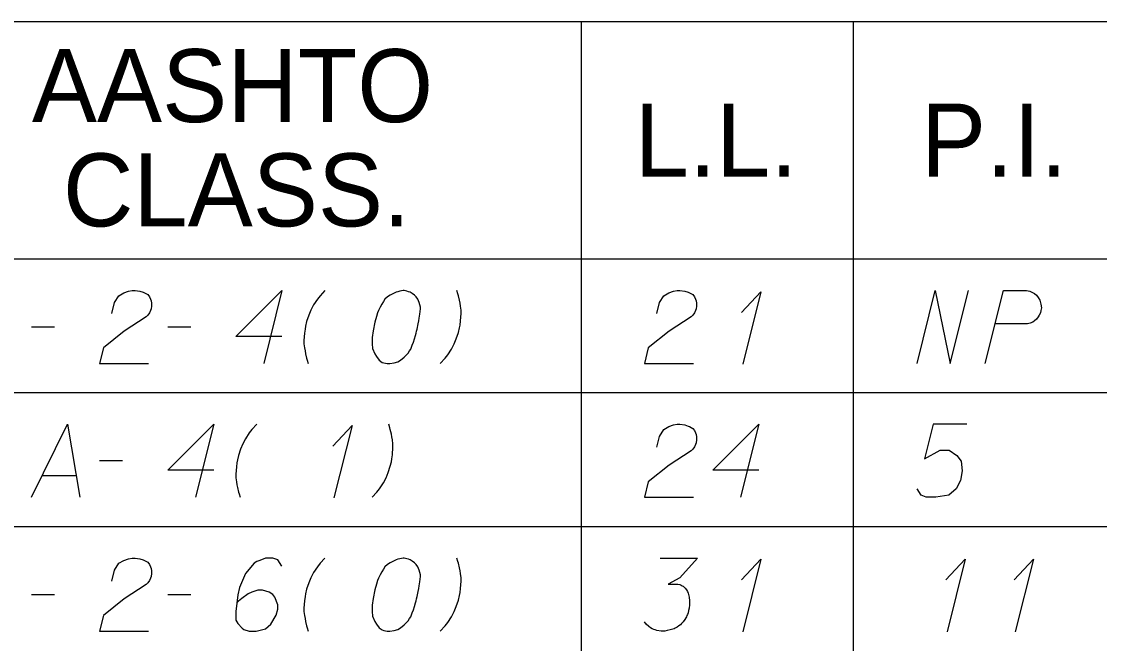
# Model space of a CAD drawing. Extents: x 2074207 to 2076812, y 516372 to 523312.
# Drawn here: x 2076453.5 to 2076524.4, y 517338.3 to 517379.2 of the extents above; entities that cross this region are included whole.
import ezdxf

# ---------------------------------------------------------------- set-up
doc = ezdxf.new("R2010")
doc.units = 0
for name, color, linetype in [('Prop DirtTable_ Soil Test Results - Outline (Major)', 7, 'Continuous'), ('Prop DirtTable_ Soil Test Results - Outline (Minor)', 7, 'Continuous'), ('Prop DirtTable_ Soil Test Results - Tx (Header - Small)', 7, 'Continuous'), ('Prop DirtTable_ Soil Test Results - Tx (Sample Data)', 7, 'Continuous')]:
    doc.layers.add(name, color=color, linetype=linetype)

msp = doc.modelspace()

# ---------------------------------------------------------------- linework, layer by layer
at = {"layer": 'Prop DirtTable_ Soil Test Results - Outline (Major)'}
msp.add_line((2076260.609, 517363.585), (2076811.903, 517363.585), dxfattribs=at)
msp.add_line((2076260.609, 517363.585), (2076811.903, 517363.585), dxfattribs=at)
at = {"layer": 'Prop DirtTable_ Soil Test Results - Outline (Minor)'}
for p, q in [((2076260.609, 517379.185), (2076811.903, 517379.185)), ((2076490.31, 517379.185), (2076490.31, 517354.785)), ((2076508.192, 517379.185), (2076508.192, 517354.785)), ((2076260.609, 517354.785), (2076811.903, 517354.785)), ((2076260.609, 517354.785), (2076811.903, 517354.785)), ((2076490.31, 517354.785), (2076490.31, 517345.985)), ((2076508.192, 517354.785), (2076508.192, 517345.985)), ((2076260.609, 517345.985), (2076811.903, 517345.985)), ((2076260.609, 517345.985), (2076811.903, 517345.985)), ((2076490.31, 517345.985), (2076490.31, 517337.185)), ((2076508.192, 517345.985), (2076508.192, 517337.185))]:
    msp.add_line(p, q, dxfattribs=at)
at = {"layer": 'Prop DirtTable_ Soil Test Results - Tx (Sample Data)'}
for points in [[(2076459.447, 517359.986), (2076459.623, 517360.704), (2076459.906, 517361.158), (2076460.223, 517361.347), (2076460.54, 517361.46), (2076460.787, 517361.498), (2076460.964, 517361.498), (2076461.281, 517361.46), (2076461.493, 517361.385), (2076461.599, 517361.347), (2076461.81, 517361.233), (2076461.916, 517361.082), (2076461.987, 517360.931), (2076462.022, 517360.818), (2076462.057, 517360.667), (2076462.057, 517360.478), (2076462.022, 517360.289), (2076461.987, 517360.175), (2076461.916, 517360.024), (2076461.81, 517359.873), (2076461.705, 517359.759), (2076460.258, 517358.815), (2076458.883, 517357.718), (2076458.636, 517356.698), (2076461.846, 517356.698)], [(2076470.629, 517358.474), (2076467.596, 517358.474), (2076470.629, 517361.498), (2076469.43, 517356.698)], [(2076473.451, 517361.498), (2076473.134, 517361.158), (2076472.958, 517360.931), (2076472.711, 517360.553), (2076472.534, 517360.213), (2076472.393, 517359.873), (2076472.252, 517359.457), (2076472.181, 517359.155), (2076472.146, 517358.966), (2076472.111, 517358.701), (2076472.076, 517358.21), (2076472.076, 517357.983), (2076472.111, 517357.718), (2076472.146, 517357.529), (2076472.181, 517357.341), (2076472.252, 517357.038), (2076472.287, 517356.925), (2076472.358, 517356.698)], [(2076478.672, 517361.498), (2076478.602, 517361.498), (2076478.39, 517361.46), (2076478.249, 517361.422), (2076478.143, 517361.385), (2076477.967, 517361.309), (2076477.755, 517361.196), (2076477.579, 517361.082), (2076477.402, 517360.931), (2076477.296, 517360.78), (2076477.191, 517360.591), (2076477.085, 517360.402), (2076476.979, 517360.175), (2076476.908, 517360.024), (2076476.838, 517359.797), (2076476.732, 517359.419), (2076476.626, 517358.852), (2076476.556, 517358.399), (2076476.556, 517357.983), (2076476.591, 517357.681), (2076476.732, 517357.341), (2076476.838, 517357.152), (2076477.014, 517356.925), (2076477.226, 517356.774), (2076477.332, 517356.736), (2076477.543, 517356.698), (2076477.72, 517356.698), (2076478.002, 517356.736), (2076478.249, 517356.811), (2076478.425, 517356.925), (2076478.672, 517357.114), (2076478.778, 517357.227), (2076478.919, 517357.378), (2076479.025, 517357.529), (2076479.095, 517357.643), (2076479.166, 517357.832), (2076479.201, 517357.907), (2076479.272, 517358.096), (2076479.342, 517358.323), (2076479.413, 517358.55), (2076479.448, 517358.701), (2076479.483, 517358.815), (2076479.519, 517358.966), (2076479.589, 517359.306), (2076479.625, 517359.495), (2076479.66, 517359.684), (2076479.695, 517359.948), (2076479.73, 517360.289), (2076479.73, 517360.402), (2076479.695, 517360.553), (2076479.66, 517360.704), (2076479.554, 517360.931), (2076479.448, 517361.082), (2076479.342, 517361.196), (2076479.201, 517361.309), (2076479.06, 517361.385), (2076478.954, 517361.422), (2076478.849, 517361.46), (2076478.672, 517361.498)], [(2076481.036, 517356.698), (2076481.353, 517357.038), (2076481.529, 517357.265), (2076481.776, 517357.643), (2076481.953, 517357.983), (2076482.094, 517358.323), (2076482.235, 517358.739), (2076482.306, 517359.041), (2076482.341, 517359.23), (2076482.376, 517359.495), (2076482.411, 517359.986), (2076482.411, 517360.213), (2076482.376, 517360.478), (2076482.341, 517360.667), (2076482.306, 517360.855), (2076482.235, 517361.158), (2076482.2, 517361.271), (2076482.129, 517361.498)], [(2076495.287, 517359.986), (2076495.463, 517360.704), (2076495.746, 517361.158), (2076496.063, 517361.347), (2076496.38, 517361.46), (2076496.627, 517361.498), (2076496.804, 517361.498), (2076497.121, 517361.46), (2076497.333, 517361.385), (2076497.439, 517361.347), (2076497.65, 517361.233), (2076497.756, 517361.082), (2076497.827, 517360.931), (2076497.862, 517360.818), (2076497.897, 517360.667), (2076497.897, 517360.478), (2076497.862, 517360.289), (2076497.827, 517360.175), (2076497.756, 517360.024), (2076497.65, 517359.873), (2076497.545, 517359.759), (2076496.098, 517358.815), (2076494.723, 517357.718), (2076494.476, 517356.698), (2076497.686, 517356.698)], [(2076500.86, 517360.062), (2076502.13, 517361.422), (2076500.931, 517356.66)], [(2076512.396, 517356.698), (2076513.595, 517361.498), (2076514.583, 517356.698), (2076515.782, 517361.498)], [(2076516.876, 517356.698), (2076518.075, 517361.498), (2076519.592, 517361.498), (2076519.803, 517361.46), (2076519.909, 517361.422), (2076520.121, 517361.309), (2076520.262, 517361.196), (2076520.368, 517361.044), (2076520.474, 517360.855), (2076520.544, 517360.591), (2076520.58, 517360.364), (2076520.544, 517360.175), (2076520.509, 517360.024), (2076520.438, 517359.873), (2076520.368, 517359.759), (2076520.262, 517359.608), (2076520.121, 517359.495), (2076520.015, 517359.419), (2076519.839, 517359.344), (2076519.662, 517359.306), (2076517.546, 517359.306)], [(2076454.156, 517359.117), (2076455.672, 517359.117)], [(2076463.116, 517359.117), (2076464.632, 517359.117)], [(2076454.156, 517347.898), (2076456.519, 517352.698), (2076457.33, 517347.898)], [(2076466.149, 517349.674), (2076463.116, 517349.674), (2076466.149, 517352.698), (2076464.95, 517347.898)], [(2076468.971, 517352.698), (2076468.654, 517352.358), (2076468.478, 517352.131), (2076468.231, 517351.753), (2076468.054, 517351.413), (2076467.913, 517351.073), (2076467.772, 517350.657), (2076467.701, 517350.355), (2076467.666, 517350.166), (2076467.631, 517349.901), (2076467.596, 517349.41), (2076467.596, 517349.183), (2076467.631, 517348.918), (2076467.666, 517348.729), (2076467.701, 517348.541), (2076467.772, 517348.238), (2076467.807, 517348.125), (2076467.878, 517347.898)], [(2076476.556, 517347.898), (2076476.873, 517348.238), (2076477.049, 517348.465), (2076477.296, 517348.843), (2076477.473, 517349.183), (2076477.614, 517349.523), (2076477.755, 517349.939), (2076477.826, 517350.241), (2076477.861, 517350.43), (2076477.896, 517350.695), (2076477.931, 517351.186), (2076477.931, 517351.413), (2076477.896, 517351.678), (2076477.861, 517351.867), (2076477.826, 517352.055), (2076477.755, 517352.358), (2076477.72, 517352.471), (2076477.649, 517352.698)], [(2076495.287, 517351.186), (2076495.463, 517351.904), (2076495.746, 517352.358), (2076496.063, 517352.547), (2076496.38, 517352.66), (2076496.627, 517352.698), (2076496.804, 517352.698), (2076497.121, 517352.66), (2076497.333, 517352.585), (2076497.439, 517352.547), (2076497.65, 517352.433), (2076497.756, 517352.282), (2076497.827, 517352.131), (2076497.862, 517352.018), (2076497.897, 517351.867), (2076497.897, 517351.678), (2076497.862, 517351.489), (2076497.827, 517351.375), (2076497.756, 517351.224), (2076497.65, 517351.073), (2076497.545, 517350.959), (2076496.098, 517350.015), (2076494.723, 517348.918), (2076494.476, 517347.898), (2076497.686, 517347.898)], [(2076501.989, 517349.674), (2076498.956, 517349.674), (2076501.989, 517352.698), (2076500.79, 517347.898)], [(2076515.676, 517352.698), (2076513.454, 517352.698), (2076512.889, 517350.43), (2076513.912, 517350.997), (2076514.512, 517350.997), (2076515.006, 517350.657), (2076515.288, 517350.279), (2076515.359, 517349.637), (2076515.253, 517348.994), (2076514.971, 517348.465), (2076514.477, 517348.049), (2076513.63, 517347.898), (2076512.995, 517347.898), (2076512.678, 517348.049), (2076512.396, 517348.465)], [(2076473.98, 517351.262), (2076475.25, 517352.622), (2076474.051, 517347.86)], [(2076458.636, 517350.317), (2076460.152, 517350.317)], [(2076454.861, 517349.334), (2076457.083, 517349.334)], [(2076459.447, 517342.386), (2076459.623, 517343.104), (2076459.906, 517343.558), (2076460.223, 517343.747), (2076460.54, 517343.86), (2076460.787, 517343.898), (2076460.964, 517343.898), (2076461.281, 517343.86), (2076461.493, 517343.785), (2076461.599, 517343.747), (2076461.81, 517343.633), (2076461.916, 517343.482), (2076461.987, 517343.331), (2076462.022, 517343.218), (2076462.057, 517343.067), (2076462.057, 517342.878), (2076462.022, 517342.689), (2076461.987, 517342.575), (2076461.916, 517342.424), (2076461.81, 517342.273), (2076461.705, 517342.159), (2076460.258, 517341.215), (2076458.883, 517340.118), (2076458.636, 517339.098), (2076461.846, 517339.098)], [(2076470.629, 517343.369), (2076470.347, 517343.785), (2076470.03, 517343.898), (2076469.536, 517343.898), (2076469.183, 517343.747), (2076468.971, 517343.671), (2076468.795, 517343.558), (2076468.231, 517342.878), (2076467.843, 517341.97), (2076467.737, 517341.479), (2076467.596, 517340.383), (2076467.596, 517339.816), (2076467.737, 517339.589), (2076468.019, 517339.287), (2076468.125, 517339.211), (2076468.478, 517339.098), (2076468.936, 517339.098), (2076469.289, 517339.174), (2076469.536, 517339.249), (2076469.889, 517339.552), (2076470.241, 517340.156), (2076470.347, 517340.534), (2076470.347, 517340.837), (2076470.171, 517341.328), (2076470.03, 517341.517), (2076469.783, 517341.668), (2076469.359, 517341.781), (2076469.042, 517341.781), (2076468.654, 517341.668), (2076468.407, 517341.555), (2076467.984, 517341.252), (2076467.772, 517341.063), (2076467.666, 517340.95)], [(2076473.451, 517343.898), (2076473.134, 517343.558), (2076472.958, 517343.331), (2076472.711, 517342.953), (2076472.534, 517342.613), (2076472.393, 517342.273), (2076472.252, 517341.857), (2076472.181, 517341.555), (2076472.146, 517341.366), (2076472.111, 517341.101), (2076472.076, 517340.61), (2076472.076, 517340.383), (2076472.111, 517340.118), (2076472.146, 517339.929), (2076472.181, 517339.741), (2076472.252, 517339.438), (2076472.287, 517339.325), (2076472.358, 517339.098)], [(2076478.672, 517343.898), (2076478.602, 517343.898), (2076478.39, 517343.86), (2076478.249, 517343.822), (2076478.143, 517343.785), (2076477.967, 517343.709), (2076477.755, 517343.596), (2076477.579, 517343.482), (2076477.402, 517343.331), (2076477.296, 517343.18), (2076477.191, 517342.991), (2076477.085, 517342.802), (2076476.979, 517342.575), (2076476.908, 517342.424), (2076476.838, 517342.197), (2076476.732, 517341.819), (2076476.626, 517341.252), (2076476.556, 517340.799), (2076476.556, 517340.383), (2076476.591, 517340.081), (2076476.732, 517339.741), (2076476.838, 517339.552), (2076477.014, 517339.325), (2076477.226, 517339.174), (2076477.332, 517339.136), (2076477.543, 517339.098), (2076477.72, 517339.098), (2076478.002, 517339.136), (2076478.249, 517339.211), (2076478.425, 517339.325), (2076478.672, 517339.514), (2076478.778, 517339.627), (2076478.919, 517339.778), (2076479.025, 517339.929), (2076479.095, 517340.043), (2076479.166, 517340.232), (2076479.201, 517340.307), (2076479.272, 517340.496), (2076479.342, 517340.723), (2076479.413, 517340.95), (2076479.448, 517341.101), (2076479.483, 517341.215), (2076479.519, 517341.366), (2076479.589, 517341.706), (2076479.625, 517341.895), (2076479.66, 517342.084), (2076479.695, 517342.348), (2076479.73, 517342.689), (2076479.73, 517342.802), (2076479.695, 517342.953), (2076479.66, 517343.104), (2076479.554, 517343.331), (2076479.448, 517343.482), (2076479.342, 517343.596), (2076479.201, 517343.709), (2076479.06, 517343.785), (2076478.954, 517343.822), (2076478.849, 517343.86), (2076478.672, 517343.898)], [(2076481.036, 517339.098), (2076481.353, 517339.438), (2076481.529, 517339.665), (2076481.776, 517340.043), (2076481.953, 517340.383), (2076482.094, 517340.723), (2076482.235, 517341.139), (2076482.306, 517341.441), (2076482.341, 517341.63), (2076482.376, 517341.895), (2076482.411, 517342.386), (2076482.411, 517342.613), (2076482.376, 517342.878), (2076482.341, 517343.067), (2076482.306, 517343.255), (2076482.235, 517343.558), (2076482.2, 517343.671), (2076482.129, 517343.898)], [(2076495.499, 517343.898), (2076497.968, 517343.898), (2076496.804, 517342.613), (2076496.028, 517342.197), (2076496.663, 517342.197), (2076496.804, 517342.159), (2076496.874, 517342.122), (2076496.945, 517342.084), (2076497.015, 517342.046), (2076497.157, 517341.933), (2076497.227, 517341.819), (2076497.298, 517341.706), (2076497.333, 517341.592), (2076497.403, 517341.328), (2076497.439, 517341.101), (2076497.439, 517340.988), (2076497.439, 517340.837), (2076497.403, 517340.61), (2076497.368, 517340.459), (2076497.333, 517340.307), (2076497.298, 517340.194), (2076497.262, 517340.118), (2076497.227, 517340.043), (2076497.192, 517339.967), (2076497.121, 517339.854), (2076497.015, 517339.703), (2076496.91, 517339.589), (2076496.839, 517339.514), (2076496.733, 517339.438), (2076496.627, 517339.363), (2076496.486, 517339.287), (2076496.416, 517339.249), (2076496.169, 517339.174), (2076495.957, 517339.136), (2076495.816, 517339.098), (2076495.569, 517339.098), (2076495.287, 517339.136), (2076495.181, 517339.174), (2076495.075, 517339.211), (2076494.969, 517339.249), (2076494.864, 517339.325), (2076494.758, 517339.4), (2076494.581, 517339.552), (2076494.476, 517339.703)], [(2076500.86, 517342.462), (2076502.13, 517343.822), (2076500.931, 517339.06)], [(2076514.3, 517342.462), (2076515.57, 517343.822), (2076514.371, 517339.06)], [(2076518.78, 517342.462), (2076520.05, 517343.822), (2076518.851, 517339.06)], [(2076454.156, 517341.517), (2076455.672, 517341.517)], [(2076463.116, 517341.517), (2076464.632, 517341.517)]]:
    msp.add_lwpolyline(points, dxfattribs=at)

# ---------------------------------------------------------------- texts
at = {"layer": 'Prop DirtTable_ Soil Test Results - Tx (Header - Small)'}
for s, p in [('AASHTO', (2076454.182, 517372.572)), ('L.L.', (2076493.827, 517368.986)), ('P.I.', (2076512.654, 517368.986)), ('CLASS.', (2076456.225, 517365.715))]:
    msp.add_text(s, height=4.8, dxfattribs=at).set_placement(p)

doc.saveas('drawing.dxf')
